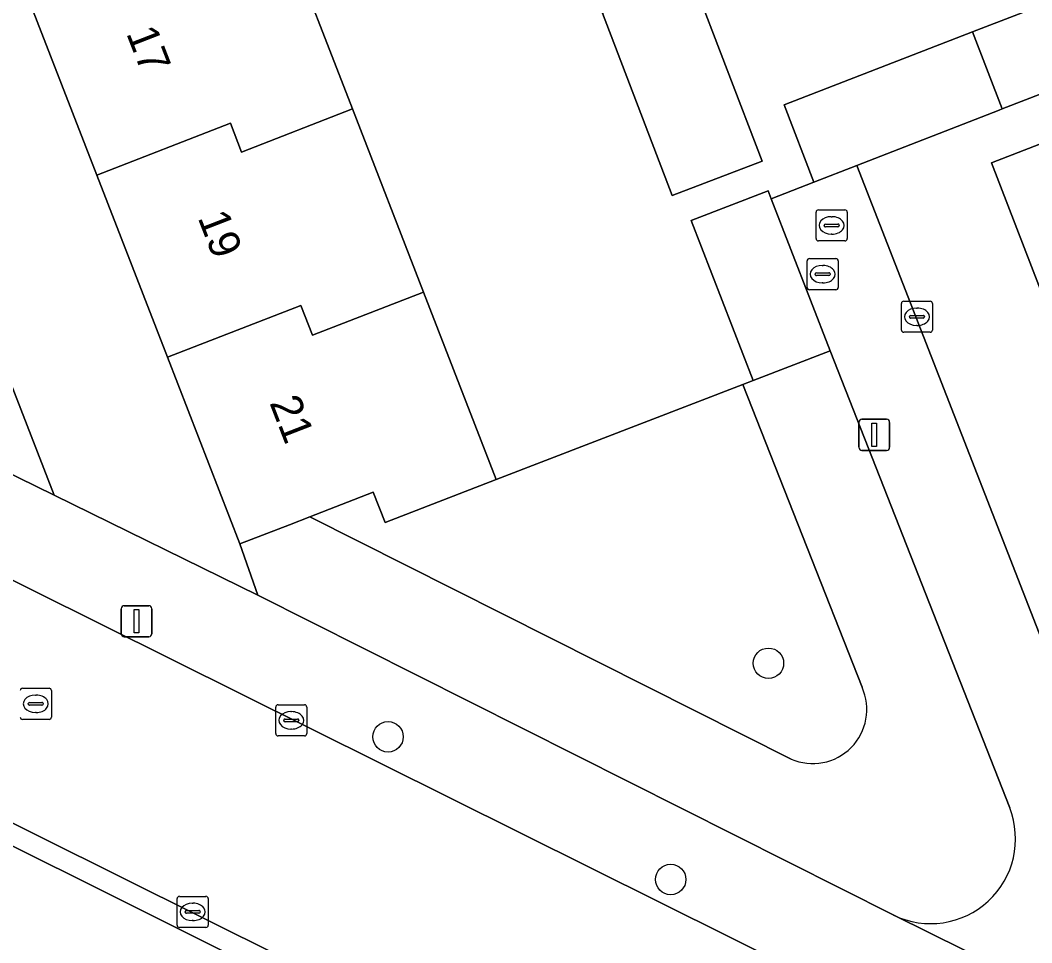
# Model space of a CAD drawing. Extents: x 162989 to 165008, y 383432 to 384338.
# Drawn here: x 164020.88 to 164053.39, y 383781.13 to 383810.77 of the extents above; entities that cross this region are included whole.
import ezdxf

# ---------------------------------------------------------------- set-up
doc = ezdxf.new("R2010")
doc.units = 0
for name, color, linetype in [('IMGEO_Boom', 7, 'Continuous'), ('IMGEO_Brandkraan', 7, 'Continuous'), ('IMGEO_Erf', 7, 'Continuous'), ('IMGEO_Groenvoorziening', 7, 'Continuous'), ('IMGEO_Kolk', 7, 'Continuous'), ('IMGEO_Lichtmast', 7, 'Continuous'), ('IMGEO_Pand', 7, 'Continuous'), ('IMGEO_Pand_nummerreeks', 7, 'Continuous'), ('IMGEO_Rijbaan_lokaal_open', 7, 'Continuous'), ('IMGEO_Rioolput', 7, 'Continuous'), ('IMGEO_Voetpad_open', 7, 'Continuous')]:
    doc.layers.add(name, color=color, linetype=linetype)

msp = doc.modelspace()

# ---------------------------------------------------------------- linework, layer by layer
at = {"layer": 'IMGEO_Boom'}
for centre in [(164044.927, 383790.112), (164032.7, 383787.749), (164041.785, 383783.164)]:
    msp.add_circle(centre, 0.489, dxfattribs=at)
at = {"layer": 'IMGEO_Brandkraan'}
for p, q in [((164046.458, 383803.756), (164046.458, 383804.608)), ((164046.533, 383804.682), (164047.385, 383804.682)), ((164047.459, 383804.608), (164047.459, 383803.756)), ((164046.946, 383804.462), (164046.971, 383804.462)), ((164046.717, 383804.176), (164046.717, 383804.188)), ((164047.155, 383804.139), (164046.757, 383804.139)), ((164046.76, 383804.225), (164047.158, 383804.225)), ((164047.201, 383804.188), (164047.201, 383804.176)), ((164047.385, 383803.682), (164046.533, 383803.682)), ((164046.969, 383803.902), (164046.944, 383803.902))]:
    msp.add_line(p, q, dxfattribs=at)
for points in [[(164046.458, 383803.756), (164046.458, 383804.608)], [(164046.533, 383804.682), (164047.385, 383804.682)], [(164047.459, 383804.608), (164047.459, 383803.756)], [(164047.385, 383803.682), (164046.533, 383803.682)]]:
    msp.add_lwpolyline(points, dxfattribs=at)
for centre, radius, start, end in [((164046.535, 383804.606), 0.0765, 91.552, 178.448), ((164046.535, 383804.606), 0.0765, 91.552, 178.448), ((164047.383, 383804.606), 0.0765, 1.552, 88.448), ((164047.383, 383804.606), 0.0765, 1.552, 88.448), ((164046.757, 383804.185), 0.0403, 85.8775, 175.7526), ((164046.754, 383804.175), 0.0366, 178.938, 274.7102), ((164047.158, 383804.182), 0.043, 264.8664, 352.4533), ((164047.162, 383804.187), 0.0386, 1.7309, 96.639), ((164046.535, 383803.758), 0.0765, 181.552, 268.448), ((164046.535, 383803.758), 0.0765, 181.552, 268.448), ((164047.383, 383803.758), 0.0765, 271.552, 358.448), ((164047.383, 383803.758), 0.0765, 271.552, 358.448)]:
    msp.add_arc(centre, radius, start, end, dxfattribs=at)
for centre, major_axis, ratio, start_param, end_param in [((164046.945, 383804.182), (-0.387, 0.002), 0.722429, 4.712389, 7.853982), ((164046.97, 383804.182), (-0.39, 0.002), 0.717154, 1.570796, 4.712389)]:
    msp.add_ellipse(centre, major_axis=major_axis, ratio=ratio, start_param=start_param, end_param=end_param, dxfattribs=at)
at = {"layer": 'IMGEO_Erf'}
for points in [[(164013.314, 383817.827), (164021.968, 383795.511), (164028.519, 383792.302), (164027.938, 383793.948), (164025.613, 383799.944), (164023.342, 383805.799), (164021.071, 383811.655)], [(164029.274, 383813.806), (164031.556, 383807.922), (164033.837, 383802.039), (164036.173, 383796.015), (164044.109, 383799.068), (164044.435, 383799.194), (164042.442, 383804.334), (164044.913, 383805.292), (164045.014, 383805.032), (164046.39, 383805.573), (164045.429, 383808.058), (164051.481, 383810.397), (164057.401, 383812.685)], [(164064.218, 383812.475), (164058.364, 383810.212), (164058.358, 383810.21), (164052.437, 383807.922), (164052.345, 383807.886), (164047.767, 383806.108), (164059.125, 383776.988), (164068.699, 383772.244)]]:
    msp.add_lwpolyline(points, dxfattribs=at)
for points in [[(164042.48, 383812.128), (164044.728, 383806.247), (164041.832, 383805.14), (164039.59, 383811.006), (164037.935, 383815.335), (164040.831, 383816.442)], [(164067.359, 383790.564), (164069.647, 383784.654), (164070.184, 383783.268), (164071.989, 383778.605), (164068.294, 383777.175), (164067.96, 383778.039), (164063.641, 383776.366), (164061.299, 383782.415), (164059.012, 383788.325), (164056.724, 383794.234), (164054.436, 383800.144), (164052.093, 383806.197), (164057.095, 383808.132), (164057.473, 383807.157), (164060.483, 383808.323), (164062.783, 383802.382), (164065.071, 383796.474)]]:
    msp.add_lwpolyline(points, close=True, dxfattribs=at)
at = {"layer": 'IMGEO_Groenvoorziening'}
for points in [[(163846.299, 383851.794), (163880.237, 383839.724), (163923.817, 383821.246), (163935.03, 383816.871), (163938.07, 383815.685), (164000, 383788.515), (164001.434, 383787.886), (164020.113, 383778.24), (164032.955, 383772.178), (164060.575, 383757.962), (164061.832, 383760.603), (164063.019, 383763.095), (164000, 383794.524), (163952.06, 383818.131)], [(164046.906, 383800.152), (164044.435, 383799.194), (164044.109, 383799.068), (164047.935, 383789.339)], [(164052.681, 383785.467), (164046.906, 383800.152)], [(164044.109, 383799.068), (164036.173, 383796.015)], [(164047.935, 383789.339), (164044.109, 383799.068)], [(164036.173, 383796.015), (164032.604, 383794.631), (164032.225, 383795.61), (164030.188, 383794.82)], [(164045.656, 383787.034), (164030.188, 383794.82), (164029.53, 383794.565), (164027.938, 383793.948), (164028.519, 383792.302), (164048.952, 383782.017)], [(164030.188, 383794.82), (164045.656, 383787.034)]]:
    msp.add_lwpolyline(points, dxfattribs=at)
for centre, radius, start, end in [((164046.354, 383788.623), 1.735, 246.2657, 24.3843), ((164046.354, 383788.623), 1.735, 246.2657, 24.3843), ((164050.141, 383784.472), 2.728, 244.1482, 21.4007)]:
    msp.add_arc(centre, radius, start, end, dxfattribs=at)
at = {"layer": 'IMGEO_Kolk'}
for p, q in [((164049.199, 383800.82), (164049.199, 383801.672)), ((164049.274, 383801.746), (164050.126, 383801.746)), ((164050.2, 383801.672), (164050.2, 383800.82)), ((164049.687, 383801.526), (164049.712, 383801.526)), ((164049.458, 383801.24), (164049.458, 383801.252)), ((164049.896, 383801.203), (164049.498, 383801.203)), ((164049.501, 383801.289), (164049.899, 383801.289)), ((164049.942, 383801.252), (164049.942, 383801.24)), ((164050.126, 383800.746), (164049.274, 383800.746)), ((164049.71, 383800.966), (164049.685, 383800.966)), ((164029.089, 383787.851), (164029.089, 383788.703)), ((164029.164, 383788.777), (164030.016, 383788.777)), ((164030.09, 383788.703), (164030.09, 383787.851)), ((164029.391, 383788.32), (164029.789, 383788.32)), ((164029.577, 383788.557), (164029.602, 383788.557)), ((164029.348, 383788.271), (164029.348, 383788.283)), ((164029.786, 383788.234), (164029.388, 383788.234)), ((164029.6, 383787.997), (164029.575, 383787.997)), ((164029.832, 383788.283), (164029.832, 383788.271)), ((164030.016, 383787.777), (164029.164, 383787.777)), ((164025.92, 383781.696), (164025.92, 383782.548)), ((164025.995, 383782.622), (164026.847, 383782.622)), ((164026.921, 383782.548), (164026.921, 383781.696)), ((164026.179, 383782.116), (164026.179, 383782.128)), ((164026.222, 383782.165), (164026.62, 383782.165)), ((164026.408, 383782.402), (164026.433, 383782.402)), ((164026.663, 383782.128), (164026.663, 383782.116)), ((164026.617, 383782.079), (164026.219, 383782.079)), ((164026.431, 383781.842), (164026.406, 383781.842)), ((164026.847, 383781.622), (164025.995, 383781.622))]:
    msp.add_line(p, q, dxfattribs=at)
for points in [[(164049.199, 383800.82), (164049.199, 383801.672)], [(164049.274, 383801.746), (164050.126, 383801.746)], [(164050.2, 383801.672), (164050.2, 383800.82)], [(164050.126, 383800.746), (164049.274, 383800.746)], [(164029.089, 383787.851), (164029.089, 383788.703)], [(164029.164, 383788.777), (164030.016, 383788.777)], [(164030.09, 383788.703), (164030.09, 383787.851)], [(164030.016, 383787.777), (164029.164, 383787.777)], [(164025.92, 383781.696), (164025.92, 383782.548)], [(164025.995, 383782.622), (164026.847, 383782.622)], [(164026.921, 383782.548), (164026.921, 383781.696)], [(164026.847, 383781.622), (164025.995, 383781.622)]]:
    msp.add_lwpolyline(points, dxfattribs=at)
for centre, radius, start, end in [((164049.276, 383801.67), 0.0765, 91.552, 178.448), ((164049.276, 383801.67), 0.0765, 91.552, 178.448), ((164050.124, 383801.67), 0.0765, 1.552, 88.448), ((164050.124, 383801.67), 0.0765, 1.552, 88.448), ((164049.498, 383801.249), 0.0403, 85.8775, 175.7526), ((164049.495, 383801.239), 0.0366, 178.938, 274.7102), ((164049.899, 383801.246), 0.043, 264.8664, 352.4533), ((164049.903, 383801.251), 0.0386, 1.7309, 96.639), ((164049.276, 383800.822), 0.0765, 181.552, 268.448), ((164049.276, 383800.822), 0.0765, 181.552, 268.448), ((164050.124, 383800.822), 0.0765, 271.552, 358.448), ((164050.124, 383800.822), 0.0765, 271.552, 358.448), ((164029.166, 383788.701), 0.0765, 91.552, 178.448), ((164029.166, 383788.701), 0.0765, 91.552, 178.448), ((164030.014, 383788.701), 0.0765, 1.552, 88.448), ((164030.014, 383788.701), 0.0765, 1.552, 88.448), ((164029.388, 383788.28), 0.0403, 85.8775, 175.7526), ((164029.793, 383788.282), 0.0386, 1.7309, 96.639), ((164029.385, 383788.27), 0.0366, 178.938, 274.7102), ((164029.789, 383788.277), 0.043, 264.8664, 352.4533), ((164029.166, 383787.853), 0.0765, 181.552, 268.448), ((164029.166, 383787.853), 0.0765, 181.552, 268.448), ((164030.014, 383787.853), 0.0765, 271.552, 358.448), ((164030.014, 383787.853), 0.0765, 271.552, 358.448), ((164025.997, 383782.546), 0.0765, 91.552, 178.448), ((164025.997, 383782.546), 0.0765, 91.552, 178.448), ((164026.845, 383782.546), 0.0765, 1.552, 88.448), ((164026.845, 383782.546), 0.0765, 1.552, 88.448), ((164026.219, 383782.125), 0.0403, 85.8775, 175.7526), ((164026.624, 383782.127), 0.0386, 1.7309, 96.639), ((164026.216, 383782.115), 0.0366, 178.938, 274.7102), ((164026.62, 383782.122), 0.043, 264.8664, 352.4533), ((164025.997, 383781.698), 0.0765, 181.552, 268.448), ((164025.997, 383781.698), 0.0765, 181.552, 268.448), ((164026.845, 383781.698), 0.0765, 271.552, 358.448), ((164026.845, 383781.698), 0.0765, 271.552, 358.448)]:
    msp.add_arc(centre, radius, start, end, dxfattribs=at)
for centre, major_axis, ratio, start_param, end_param in [((164049.686, 383801.246), (-0.387, 0.002), 0.722429, 4.712389, 7.853982), ((164049.711, 383801.246), (-0.39, 0.002), 0.717154, 1.570796, 4.712389), ((164029.576, 383788.277), (-0.387, 0.002), 0.722429, 4.712389, 7.853982), ((164029.601, 383788.277), (-0.39, 0.002), 0.717154, 1.570796, 4.712389), ((164026.407, 383782.122), (-0.387, 0.002), 0.722429, 4.712389, 7.853982), ((164026.432, 383782.122), (-0.39, 0.002), 0.717154, 1.570796, 4.712389)]:
    msp.add_ellipse(centre, major_axis=major_axis, ratio=ratio, start_param=start_param, end_param=end_param, dxfattribs=at)
at = {"layer": 'IMGEO_Lichtmast'}
for p, q in [((164047.832, 383797.051), (164047.832, 383797.851)), ((164047.832, 383797.851), (164047.832, 383797.051)), ((164047.932, 383797.951), (164048.722, 383797.951)), ((164048.722, 383797.951), (164047.932, 383797.951)), ((164048.822, 383797.851), (164048.822, 383797.051)), ((164048.822, 383797.051), (164048.822, 383797.851)), ((164048.722, 383796.951), (164047.932, 383796.951)), ((164047.932, 383796.951), (164048.722, 383796.951)), ((164024.22, 383791.96), (164025.01, 383791.96)), ((164025.01, 383791.96), (164024.22, 383791.96)), ((164024.12, 383791.06), (164024.12, 383791.86)), ((164024.12, 383791.86), (164024.12, 383791.06)), ((164025.11, 383791.86), (164025.11, 383791.06)), ((164025.11, 383791.06), (164025.11, 383791.86)), ((164025.01, 383790.96), (164024.22, 383790.96)), ((164024.22, 383790.96), (164025.01, 383790.96))]:
    msp.add_line(p, q, dxfattribs=at)
for points in [[(164048.252, 383797.826), (164048.402, 383797.826), (164048.402, 383797.076), (164048.252, 383797.076), (164048.252, 383797.826)], [(164024.54, 383791.835), (164024.69, 383791.835), (164024.69, 383791.085), (164024.54, 383791.085), (164024.54, 383791.835)]]:
    msp.add_lwpolyline(points, dxfattribs=at)
for centre, start, end in [((164047.932, 383797.851), 90, 180), ((164047.932, 383797.851), 90, 180), ((164048.722, 383797.851), 0, 90), ((164048.722, 383797.851), 360, 90), ((164047.932, 383797.051), 180, 270), ((164047.932, 383797.051), 180, 270), ((164048.722, 383797.051), 270, 0), ((164048.722, 383797.051), 270, 0), ((164024.22, 383791.86), 90, 180), ((164024.22, 383791.86), 90, 180), ((164025.01, 383791.86), 0, 90), ((164025.01, 383791.86), 360, 90), ((164024.22, 383791.06), 180, 270), ((164024.22, 383791.06), 180, 270), ((164025.01, 383791.06), 270, 0), ((164025.01, 383791.06), 270, 0)]:
    msp.add_arc(centre, 0.1, start, end, dxfattribs=at)
at = {"layer": 'IMGEO_Pand'}
for points in [[(164029.274, 383813.806), (164025.703, 383812.421), (164025.365, 383813.318), (164021.071, 383811.655), (164023.342, 383805.799), (164027.634, 383807.462), (164027.986, 383806.537), (164031.556, 383807.922)], [(164057.401, 383812.685), (164051.481, 383810.397), (164052.437, 383807.922), (164058.358, 383810.21)], [(164042.48, 383812.128), (164039.59, 383811.006), (164041.832, 383805.14), (164044.728, 383806.247)], [(164052.437, 383807.922), (164051.481, 383810.397), (164045.429, 383808.058), (164046.39, 383805.573), (164047.767, 383806.108), (164052.345, 383807.886)], [(164062.783, 383802.382), (164060.483, 383808.323), (164057.473, 383807.157), (164057.095, 383808.132), (164052.093, 383806.197), (164054.436, 383800.144), (164058.742, 383801.814), (164059.092, 383800.954)], [(164025.613, 383799.944), (164029.902, 383801.606), (164030.268, 383800.654), (164033.837, 383802.039), (164031.556, 383807.922), (164027.986, 383806.537), (164027.634, 383807.462), (164023.342, 383805.799)], [(164045.014, 383805.032), (164044.913, 383805.292), (164042.442, 383804.334), (164044.435, 383799.194), (164046.906, 383800.152)], [(164025.613, 383799.944), (164027.938, 383793.948), (164029.53, 383794.565), (164030.188, 383794.82), (164032.225, 383795.61), (164032.604, 383794.631), (164036.173, 383796.015), (164033.837, 383802.039), (164030.268, 383800.654), (164029.902, 383801.606)]]:
    msp.add_lwpolyline(points, close=True, dxfattribs=at)
at = {"layer": 'IMGEO_Rijbaan_lokaal_open'}
msp.add_lwpolyline([(164063.775, 383763.5), (164066.845, 383769.801), (164066.141, 383770.136), (164016.764, 383794.701), (164013.655, 383788.447), (164063.32, 383763.72)], close=True, dxfattribs=at)
at = {"layer": 'IMGEO_Rioolput'}
for p, q in [((164046.169, 383802.188), (164046.169, 383803.04)), ((164046.244, 383803.114), (164047.096, 383803.114)), ((164047.17, 383803.04), (164047.17, 383802.188)), ((164046.428, 383802.608), (164046.428, 383802.62)), ((164046.471, 383802.657), (164046.869, 383802.657)), ((164046.657, 383802.894), (164046.682, 383802.894)), ((164046.912, 383802.62), (164046.912, 383802.608)), ((164046.866, 383802.571), (164046.468, 383802.571)), ((164046.68, 383802.334), (164046.655, 383802.334)), ((164047.096, 383802.114), (164046.244, 383802.114)), ((164020.952, 383789.308), (164021.804, 383789.308)), ((164021.365, 383789.088), (164021.39, 383789.088)), ((164021.878, 383789.234), (164021.878, 383788.382)), ((164021.136, 383788.802), (164021.136, 383788.814)), ((164021.574, 383788.765), (164021.176, 383788.765)), ((164021.179, 383788.851), (164021.577, 383788.851)), ((164021.62, 383788.814), (164021.62, 383788.802)), ((164021.804, 383788.308), (164020.952, 383788.308)), ((164021.388, 383788.528), (164021.363, 383788.528))]:
    msp.add_line(p, q, dxfattribs=at)
for points in [[(164046.169, 383802.188), (164046.169, 383803.04)], [(164046.244, 383803.114), (164047.096, 383803.114)], [(164047.17, 383803.04), (164047.17, 383802.188)], [(164047.096, 383802.114), (164046.244, 383802.114)], [(164020.952, 383789.308), (164021.804, 383789.308)], [(164021.878, 383789.234), (164021.878, 383788.382)], [(164021.804, 383788.308), (164020.952, 383788.308)]]:
    msp.add_lwpolyline(points, dxfattribs=at)
for centre, radius, start, end in [((164046.246, 383803.038), 0.0765, 91.552, 178.448), ((164046.246, 383803.038), 0.0765, 91.552, 178.448), ((164047.094, 383803.038), 0.0765, 1.552, 88.448), ((164047.094, 383803.038), 0.0765, 1.552, 88.448), ((164046.468, 383802.617), 0.0403, 85.8775, 175.7526), ((164046.465, 383802.607), 0.0366, 178.938, 274.7102), ((164046.869, 383802.614), 0.043, 264.8664, 352.4533), ((164046.873, 383802.619), 0.0386, 1.7309, 96.639), ((164046.246, 383802.19), 0.0765, 181.552, 268.448), ((164046.246, 383802.19), 0.0765, 181.552, 268.448), ((164047.094, 383802.19), 0.0765, 271.552, 358.448), ((164047.094, 383802.19), 0.0765, 271.552, 358.448), ((164020.954, 383789.232), 0.0765, 91.552, 178.448), ((164020.954, 383789.232), 0.0765, 91.552, 178.448), ((164021.802, 383789.232), 0.0765, 1.552, 88.448), ((164021.802, 383789.232), 0.0765, 1.552, 88.448), ((164021.176, 383788.811), 0.0403, 85.8775, 175.7526), ((164021.173, 383788.801), 0.0366, 178.938, 274.7102), ((164021.577, 383788.808), 0.043, 264.8664, 352.4533), ((164021.581, 383788.813), 0.0386, 1.7309, 96.639), ((164020.954, 383788.384), 0.0765, 181.552, 268.448), ((164020.954, 383788.384), 0.0765, 181.552, 268.448), ((164021.802, 383788.384), 0.0765, 271.552, 358.448), ((164021.802, 383788.384), 0.0765, 271.552, 358.448)]:
    msp.add_arc(centre, radius, start, end, dxfattribs=at)
for centre, major_axis, ratio, start_param, end_param in [((164046.656, 383802.614), (-0.387, 0.002), 0.722429, 4.712389, 7.853982), ((164046.681, 383802.614), (-0.39, 0.002), 0.717154, 1.570796, 4.712389), ((164021.364, 383788.808), (-0.387, 0.002), 0.722429, 4.712389, 7.853982), ((164021.389, 383788.808), (-0.39, 0.002), 0.717154, 1.570796, 4.712389)]:
    msp.add_ellipse(centre, major_axis=major_axis, ratio=ratio, start_param=start_param, end_param=end_param, dxfattribs=at)
at = {"layer": 'IMGEO_Voetpad_open'}
for points in [[(164068.699, 383772.244), (164059.125, 383776.988), (164048.952, 383782.017), (164028.519, 383792.302), (164021.968, 383795.511), (164005.358, 383803.649), (163995.788, 383808.444), (163995.474, 383808.601), (163983.75, 383814.472), (163975.31, 383818.707), (163961.447, 383825.482), (163956.693, 383827.805)], [(163956.826, 383824.537), (163958.923, 383823.513), (163961.404, 383822.3), (163963.039, 383821.502), (163970.395, 383817.873), (163982.59, 383811.732), (164000, 383803.041), (164014.159, 383795.997), (164016.764, 383794.701), (164066.141, 383770.136), (164066.845, 383769.801), (164069.456, 383768.768)], [(163952.06, 383818.131), (164000, 383794.524), (164063.019, 383763.095), (164063.475, 383762.872), (164063.775, 383763.5), (164063.32, 383763.72), (164013.655, 383788.447)], [(164047.767, 383806.108), (164046.39, 383805.573), (164045.014, 383805.032), (164046.906, 383800.152), (164052.681, 383785.467)], [(164048.952, 383782.017), (164059.125, 383776.988), (164047.767, 383806.108)]]:
    msp.add_lwpolyline(points, dxfattribs=at)
msp.add_lwpolyline([(164013.314, 383817.827), (164011.927, 383821.53), (164006.276, 383819.348), (164004.357, 383811.748), (164000, 383810.058), (163995.788, 383808.444), (164005.358, 383803.649), (164021.968, 383795.511)], close=True, dxfattribs=at)
msp.add_arc((164050.141, 383784.472), 2.728, 244.1482, 21.4007, dxfattribs=at)

# ---------------------------------------------------------------- texts
at = {"layer": 'IMGEO_Pand_nummerreeks'}
for s, p in [('17', (164024.276, 383810.359)), ('19', (164026.574, 383804.433)), ('21', (164028.88, 383798.486))]:
    msp.add_text(s, height=1, rotation=291.1962, dxfattribs=at).set_placement(p)

doc.saveas('drawing.dxf')
